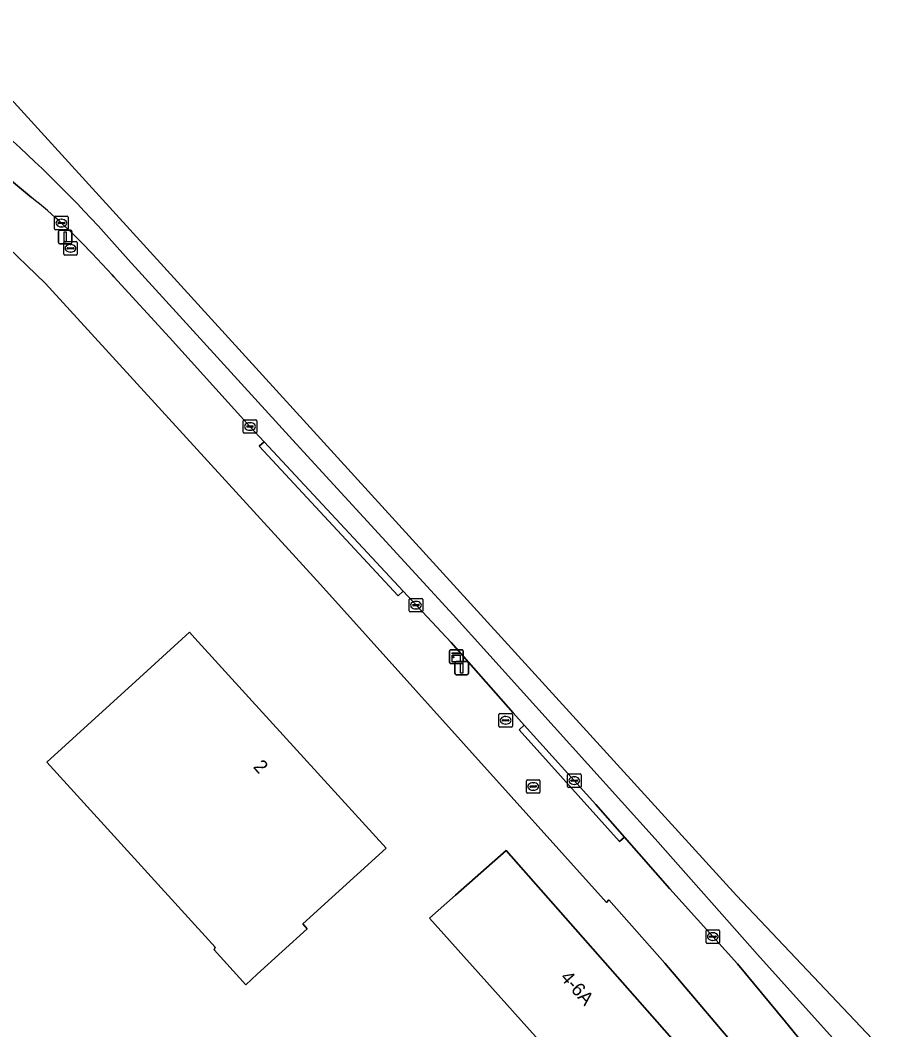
# Model space of a CAD drawing. Extents: x 161347 to 161881, y 382161 to 382804.
# Drawn here: x 161569.6 to 161633.8, y 382662 to 382736.8 of the extents above; entities that cross this region are included whole.
import ezdxf

# ---------------------------------------------------------------- set-up
doc = ezdxf.new("R2010")
doc.units = 0
for name, color, linetype in [('IMGEO_Brandkraan', 7, 'Continuous'), ('IMGEO_Erf', 7, 'Continuous'), ('IMGEO_Fietspad_gesloten', 7, 'Continuous'), ('IMGEO_Kast', 7, 'Continuous'), ('IMGEO_Kolk', 7, 'Continuous'), ('IMGEO_Lichtmast', 7, 'Continuous'), ('IMGEO_Pand', 7, 'Continuous'), ('IMGEO_Pand_nummerreeks', 7, 'Continuous'), ('IMGEO_Rijbaan_lokaal_gesloten', 7, 'Continuous'), ('IMGEO_Rioolput', 7, 'Continuous'), ('IMGEO_Voetpad_open', 7, 'Continuous')]:
    doc.layers.add(name, color=color, linetype=linetype)

msp = doc.modelspace()

# ---------------------------------------------------------------- linework, layer by layer
at = {"layer": 'IMGEO_Brandkraan'}
for p, q in [((161607.087, 382679.598), (161607.087, 382680.45)), ((161607.162, 382680.524), (161608.014, 382680.524)), ((161607.346, 382680.018), (161607.346, 382680.03)), ((161607.784, 382679.981), (161607.386, 382679.981)), ((161607.389, 382680.067), (161607.787, 382680.067)), ((161607.575, 382680.304), (161607.6, 382680.304)), ((161607.83, 382680.03), (161607.83, 382680.018)), ((161608.088, 382680.45), (161608.088, 382679.598)), ((161608.014, 382679.524), (161607.162, 382679.524)), ((161607.598, 382679.744), (161607.573, 382679.744))]:
    msp.add_line(p, q, dxfattribs=at)
for points in [[(161607.087, 382679.598), (161607.087, 382680.45)], [(161607.162, 382680.524), (161608.014, 382680.524)], [(161608.088, 382680.45), (161608.088, 382679.598)], [(161608.014, 382679.524), (161607.162, 382679.524)]]:
    msp.add_lwpolyline(points, dxfattribs=at)
for centre, radius, start, end in [((161607.164, 382680.448), 0.0765, 91.55205, 178.44795), ((161607.164, 382680.448), 0.0765, 91.55205, 178.44795), ((161607.386, 382680.027), 0.0403, 85.87752, 175.75265), ((161607.383, 382680.017), 0.0366, 178.93798, 274.71019), ((161607.787, 382680.024), 0.043, 264.86636, 352.45326), ((161607.791, 382680.029), 0.0386, 1.73085, 96.63898), ((161608.012, 382680.448), 0.0765, 1.55205, 88.44795), ((161608.012, 382680.448), 0.0765, 1.55205, 88.44795), ((161607.164, 382679.6), 0.0765, 181.55205, 268.44795), ((161607.164, 382679.6), 0.0765, 181.55205, 268.44795), ((161608.012, 382679.6), 0.0765, 271.55205, 358.44795), ((161608.012, 382679.6), 0.0765, 271.55205, 358.44795)]:
    msp.add_arc(centre, radius, start, end, dxfattribs=at)
for centre, major_axis, ratio, start_param, end_param in [((161607.574, 382680.024), (-0.387, 0.002), 0.722429, 4.712389, 7.853982), ((161607.599, 382680.024), (-0.39, 0.002), 0.717154, 1.570796, 4.712389)]:
    msp.add_ellipse(centre, major_axis=major_axis, ratio=ratio, start_param=start_param, end_param=end_param, dxfattribs=at)
at = {"layer": 'IMGEO_Erf'}
for points in [[(161591.856, 382694.988), (161571.485, 382717.274), (161568.031, 382720.568), (161555.239, 382731.179), (161554.063, 382732.154)], [(161628.148, 382654.156), (161617.321, 382666.942), (161613.19, 382671.62), (161613.021, 382671.42), (161591.856, 382694.988)]]:
    msp.add_lwpolyline(points, dxfattribs=at)
for points in [[(161571.579, 382681.821), (161578.45, 382688.079), (161582.146, 382691.445), (161582.55, 382691.001), (161586.536, 382686.624), (161596.704, 382675.461), (161590.534, 382669.841), (161590.862, 382669.482), (161587.166, 382666.115), (161586.317, 382665.342), (161583.975, 382667.913), (161584.045, 382668.134)], [(161613.901, 382654.655), (161599.917, 382670.282), (161601.837, 382671.975), (161605.587, 382675.281), (161621.16, 382657.617), (161617.611, 382654.487), (161621.256, 382649.017), (161611.371, 382642.428), (161608.598, 382646.589), (161606.558, 382649.651)]]:
    msp.add_lwpolyline(points, close=True, dxfattribs=at)
at = {"layer": 'IMGEO_Fietspad_gesloten'}
for points in [[(161566.876, 382729.794), (161565.588, 382730.912), (161565.541, 382730.953), (161563.827, 382729.146), (161570.459, 382723.644)], [(161706.007, 382577.787), (161673.989, 382613.712), (161653.899, 382634.564), (161636.579, 382653.807), (161636.242, 382654.182), (161624.391, 382667.348), (161616.607, 382676.142), (161601.665, 382692.722), (161589.767, 382705.692), (161577.619, 382719.049), (161575.378, 382721.548)], [(161574.947, 382719.489), (161576.417, 382717.907), (161576.552, 382717.761), (161580.679, 382713.283), (161586.624, 382706.683), (161587.674, 382705.553), (161597.956, 382694.49), (161601.503, 382690.673), (161606.094, 382685.466), (161606.913, 382684.561), (161612.225, 382678.689), (161614.343, 382676.276), (161617.707, 382672.442), (161622.699, 382666.884), (161626.262, 382662.585), (161628.402, 382659.955), (161631.077, 382656.546), (161631.214, 382656.385), (161631.541, 382655.956), (161631.782, 382655.692), (161639.863, 382646.847)]]:
    msp.add_lwpolyline(points, dxfattribs=at)
for centre, radius, start, end in [((161490.366, 382642.402), 116.151, 42.95321, 48.79823), ((161543.579, 382690.108), 42.979, 43.12627, 51.28657)]:
    msp.add_arc(centre, radius, start, end, dxfattribs=at)
at = {"layer": 'IMGEO_Kast'}
for p, q in [((161601.397, 382689.21), (161601.397, 382690.051)), ((161601.397, 382690.051), (161601.397, 382689.21)), ((161601.472, 382690.135), (161602.313, 382690.135)), ((161602.313, 382690.135), (161601.472, 382690.135)), ((161602.397, 382690.06), (161602.397, 382689.219)), ((161602.397, 382689.219), (161602.397, 382690.06)), ((161602.322, 382689.135), (161601.481, 382689.135)), ((161601.481, 382689.135), (161602.322, 382689.135))]:
    msp.add_line(p, q, dxfattribs=at)
for points in [[(161601.592, 382689.925), (161602.192, 382689.925), (161602.192, 382689.84), (161601.592, 382689.84), (161601.592, 382689.925)], [(161601.592, 382689.75), (161602.192, 382689.75), (161602.192, 382689.261), (161601.592, 382689.261), (161601.592, 382689.75)]]:
    msp.add_lwpolyline(points, dxfattribs=at)
msp.add_circle((161601.676, 382689.599), 0.0377, dxfattribs=at)
for centre, start, end in [((161601.475, 382690.057), 92.4484, 184.28452), ((161601.475, 382690.057), 92.4484, 184.28452), ((161602.319, 382690.057), 2.4484, 94.28452), ((161602.319, 382690.057), 2.4484, 94.28452), ((161601.475, 382689.213), 182.4484, 274.28452), ((161601.475, 382689.213), 182.4484, 274.28452), ((161602.319, 382689.213), 272.4484, 4.28452), ((161602.319, 382689.213), 272.4484, 4.28452)]:
    msp.add_arc(centre, 0.0779, start, end, dxfattribs=at)
at = {"layer": 'IMGEO_Kolk'}
for p, q in [((161572.167, 382721.321), (161572.167, 382722.173)), ((161572.242, 382722.247), (161573.094, 382722.247)), ((161572.426, 382721.741), (161572.426, 382721.753)), ((161572.864, 382721.704), (161572.466, 382721.704)), ((161572.469, 382721.79), (161572.867, 382721.79)), ((161572.655, 382722.027), (161572.68, 382722.027)), ((161572.91, 382721.753), (161572.91, 382721.741)), ((161573.168, 382722.173), (161573.168, 382721.321)), ((161573.094, 382721.247), (161572.242, 382721.247)), ((161572.678, 382721.467), (161572.653, 382721.467)), ((161586.126, 382706.256), (161586.126, 382707.108)), ((161586.201, 382707.182), (161587.053, 382707.182)), ((161586.428, 382706.725), (161586.826, 382706.725)), ((161586.614, 382706.962), (161586.639, 382706.962)), ((161587.127, 382707.108), (161587.127, 382706.256)), ((161587.053, 382706.182), (161586.201, 382706.182)), ((161586.385, 382706.676), (161586.385, 382706.688)), ((161586.823, 382706.639), (161586.425, 382706.639)), ((161586.637, 382706.402), (161586.612, 382706.402)), ((161586.869, 382706.688), (161586.869, 382706.676)), ((161598.406, 382693.021), (161598.406, 382693.873)), ((161598.481, 382693.947), (161599.333, 382693.947)), ((161598.665, 382693.441), (161598.665, 382693.453)), ((161599.103, 382693.404), (161598.705, 382693.404)), ((161598.708, 382693.49), (161599.106, 382693.49)), ((161598.894, 382693.727), (161598.919, 382693.727)), ((161599.149, 382693.453), (161599.149, 382693.441)), ((161599.407, 382693.873), (161599.407, 382693.021)), ((161599.333, 382692.947), (161598.481, 382692.947)), ((161598.917, 382693.167), (161598.892, 382693.167)), ((161610.124, 382680.03), (161610.124, 382680.882)), ((161610.199, 382680.956), (161611.051, 382680.956)), ((161610.612, 382680.736), (161610.637, 382680.736)), ((161611.125, 382680.882), (161611.125, 382680.03)), ((161611.051, 382679.956), (161610.199, 382679.956)), ((161610.383, 382680.45), (161610.383, 382680.462)), ((161610.821, 382680.413), (161610.423, 382680.413)), ((161610.426, 382680.499), (161610.824, 382680.499)), ((161610.635, 382680.176), (161610.61, 382680.176)), ((161610.867, 382680.462), (161610.867, 382680.45)), ((161620.382, 382668.478), (161620.382, 382669.33)), ((161620.457, 382669.404), (161621.309, 382669.404)), ((161621.383, 382669.33), (161621.383, 382668.478)), ((161620.641, 382668.898), (161620.641, 382668.91)), ((161621.079, 382668.861), (161620.681, 382668.861)), ((161620.684, 382668.947), (161621.082, 382668.947)), ((161620.893, 382668.624), (161620.868, 382668.624)), ((161620.87, 382669.184), (161620.895, 382669.184)), ((161621.125, 382668.91), (161621.125, 382668.898)), ((161621.309, 382668.404), (161620.457, 382668.404))]:
    msp.add_line(p, q, dxfattribs=at)
for points in [[(161572.167, 382721.321), (161572.167, 382722.173)], [(161572.242, 382722.247), (161573.094, 382722.247)], [(161573.168, 382722.173), (161573.168, 382721.321)], [(161573.094, 382721.247), (161572.242, 382721.247)], [(161586.126, 382706.256), (161586.126, 382707.108)], [(161586.201, 382707.182), (161587.053, 382707.182)], [(161587.127, 382707.108), (161587.127, 382706.256)], [(161587.053, 382706.182), (161586.201, 382706.182)], [(161598.406, 382693.021), (161598.406, 382693.873)], [(161598.481, 382693.947), (161599.333, 382693.947)], [(161599.407, 382693.873), (161599.407, 382693.021)], [(161599.333, 382692.947), (161598.481, 382692.947)], [(161610.124, 382680.03), (161610.124, 382680.882)], [(161610.199, 382680.956), (161611.051, 382680.956)], [(161611.125, 382680.882), (161611.125, 382680.03)], [(161611.051, 382679.956), (161610.199, 382679.956)], [(161620.382, 382668.478), (161620.382, 382669.33)], [(161620.457, 382669.404), (161621.309, 382669.404)], [(161621.383, 382669.33), (161621.383, 382668.478)], [(161621.309, 382668.404), (161620.457, 382668.404)]]:
    msp.add_lwpolyline(points, dxfattribs=at)
for centre, radius, start, end in [((161572.244, 382722.171), 0.0765, 91.55205, 178.44795), ((161572.244, 382722.171), 0.0765, 91.55205, 178.44795), ((161572.466, 382721.75), 0.0403, 85.87752, 175.75265), ((161572.463, 382721.74), 0.0366, 178.93798, 274.71019), ((161572.867, 382721.747), 0.043, 264.86636, 352.45326), ((161572.871, 382721.752), 0.0386, 1.73085, 96.63898), ((161573.092, 382722.171), 0.0765, 1.55205, 88.44795), ((161573.092, 382722.171), 0.0765, 1.55205, 88.44795), ((161572.244, 382721.323), 0.0765, 181.55205, 268.44795), ((161572.244, 382721.323), 0.0765, 181.55205, 268.44795), ((161573.092, 382721.323), 0.0765, 271.55205, 358.44795), ((161573.092, 382721.323), 0.0765, 271.55205, 358.44795), ((161586.203, 382707.106), 0.0765, 91.55205, 178.44795), ((161586.203, 382707.106), 0.0765, 91.55205, 178.44795), ((161586.425, 382706.685), 0.0403, 85.87752, 175.75265), ((161586.83, 382706.687), 0.0386, 1.73085, 96.63898), ((161587.051, 382707.106), 0.0765, 1.55205, 88.44795), ((161587.051, 382707.106), 0.0765, 1.55205, 88.44795), ((161586.203, 382706.258), 0.0765, 181.55205, 268.44795), ((161586.203, 382706.258), 0.0765, 181.55205, 268.44795), ((161586.422, 382706.675), 0.0366, 178.93798, 274.71019), ((161586.826, 382706.682), 0.043, 264.86636, 352.45326), ((161587.051, 382706.258), 0.0765, 271.55205, 358.44795), ((161587.051, 382706.258), 0.0765, 271.55205, 358.44795), ((161598.483, 382693.871), 0.0765, 91.55205, 178.44795), ((161598.483, 382693.871), 0.0765, 91.55205, 178.44795), ((161598.705, 382693.45), 0.0403, 85.87752, 175.75265), ((161598.702, 382693.44), 0.0366, 178.93798, 274.71019), ((161599.106, 382693.447), 0.043, 264.86636, 352.45326), ((161599.11, 382693.452), 0.0386, 1.73085, 96.63898), ((161599.331, 382693.871), 0.0765, 1.55205, 88.44795), ((161599.331, 382693.871), 0.0765, 1.55205, 88.44795), ((161598.483, 382693.023), 0.0765, 181.55205, 268.44795), ((161598.483, 382693.023), 0.0765, 181.55205, 268.44795), ((161599.331, 382693.023), 0.0765, 271.55205, 358.44795), ((161599.331, 382693.023), 0.0765, 271.55205, 358.44795), ((161610.201, 382680.88), 0.0765, 91.55205, 178.44795), ((161610.201, 382680.88), 0.0765, 91.55205, 178.44795), ((161611.049, 382680.88), 0.0765, 1.55205, 88.44795), ((161611.049, 382680.88), 0.0765, 1.55205, 88.44795), ((161610.201, 382680.032), 0.0765, 181.55205, 268.44795), ((161610.201, 382680.032), 0.0765, 181.55205, 268.44795), ((161610.423, 382680.459), 0.0403, 85.87752, 175.75265), ((161610.42, 382680.449), 0.0366, 178.93798, 274.71019), ((161610.824, 382680.456), 0.043, 264.86636, 352.45326), ((161610.828, 382680.461), 0.0386, 1.73085, 96.63898), ((161611.049, 382680.032), 0.0765, 271.55205, 358.44795), ((161611.049, 382680.032), 0.0765, 271.55205, 358.44795), ((161620.459, 382669.328), 0.0765, 91.55205, 178.44795), ((161620.459, 382669.328), 0.0765, 91.55205, 178.44795), ((161621.307, 382669.328), 0.0765, 1.55205, 88.44795), ((161621.307, 382669.328), 0.0765, 1.55205, 88.44795), ((161620.681, 382668.907), 0.0403, 85.87752, 175.75265), ((161620.678, 382668.897), 0.0366, 178.93798, 274.71019), ((161621.082, 382668.904), 0.043, 264.86636, 352.45326), ((161621.086, 382668.909), 0.0386, 1.73085, 96.63898), ((161620.459, 382668.48), 0.0765, 181.55205, 268.44795), ((161620.459, 382668.48), 0.0765, 181.55205, 268.44795), ((161621.307, 382668.48), 0.0765, 271.55205, 358.44795), ((161621.307, 382668.48), 0.0765, 271.55205, 358.44795)]:
    msp.add_arc(centre, radius, start, end, dxfattribs=at)
for centre, major_axis, ratio, start_param, end_param in [((161572.654, 382721.747), (-0.387, 0.002), 0.722429, 4.712389, 7.853982), ((161572.679, 382721.747), (-0.39, 0.002), 0.717154, 1.570796, 4.712389), ((161586.613, 382706.682), (-0.387, 0.002), 0.722429, 4.712389, 7.853982), ((161586.638, 382706.682), (-0.39, 0.002), 0.717154, 1.570796, 4.712389), ((161598.893, 382693.447), (-0.387, 0.002), 0.722429, 4.712389, 7.853982), ((161598.918, 382693.447), (-0.39, 0.002), 0.717154, 1.570796, 4.712389), ((161610.611, 382680.456), (-0.387, 0.002), 0.722429, 4.712389, 7.853982), ((161610.636, 382680.456), (-0.39, 0.002), 0.717154, 1.570796, 4.712389), ((161620.869, 382668.904), (-0.387, 0.002), 0.722429, 4.712389, 7.853982), ((161620.894, 382668.904), (-0.39, 0.002), 0.717154, 1.570796, 4.712389)]:
    msp.add_ellipse(centre, major_axis=major_axis, ratio=ratio, start_param=start_param, end_param=end_param, dxfattribs=at)
at = {"layer": 'IMGEO_Lichtmast'}
for p, q in [((161572.443, 382720.315), (161572.443, 382721.115)), ((161572.443, 382721.115), (161572.443, 382720.315)), ((161572.543, 382721.215), (161573.333, 382721.215)), ((161573.333, 382721.215), (161572.543, 382721.215)), ((161573.433, 382721.115), (161573.433, 382720.315)), ((161573.433, 382720.315), (161573.433, 382721.115)), ((161573.333, 382720.215), (161572.543, 382720.215)), ((161572.543, 382720.215), (161573.333, 382720.215)), ((161601.796, 382688.388), (161601.796, 382689.188)), ((161601.796, 382689.188), (161601.796, 382688.388)), ((161601.896, 382689.288), (161602.686, 382689.288)), ((161602.686, 382689.288), (161601.896, 382689.288)), ((161602.786, 382689.188), (161602.786, 382688.388)), ((161602.786, 382688.388), (161602.786, 382689.188)), ((161602.686, 382688.288), (161601.896, 382688.288)), ((161601.896, 382688.288), (161602.686, 382688.288))]:
    msp.add_line(p, q, dxfattribs=at)
for points in [[(161572.863, 382721.09), (161573.013, 382721.09), (161573.013, 382720.34), (161572.863, 382720.34), (161572.863, 382721.09)], [(161602.216, 382689.163), (161602.366, 382689.163), (161602.366, 382688.413), (161602.216, 382688.413), (161602.216, 382689.163)]]:
    msp.add_lwpolyline(points, dxfattribs=at)
for centre, start, end in [((161572.543, 382721.115), 90, 180), ((161572.543, 382721.115), 90, 180), ((161573.333, 382721.115), 0, 90), ((161573.333, 382721.115), 360, 90), ((161572.543, 382720.315), 180, 270), ((161572.543, 382720.315), 180, 270), ((161573.333, 382720.315), 270, 0), ((161573.333, 382720.315), 270, 0), ((161601.896, 382689.188), 90, 180), ((161601.896, 382689.188), 90, 180), ((161602.686, 382689.188), 0, 90), ((161602.686, 382689.188), 360, 90), ((161601.896, 382688.388), 180, 270), ((161601.896, 382688.388), 180, 270), ((161602.686, 382688.388), 270, 0), ((161602.686, 382688.388), 270, 0)]:
    msp.add_arc(centre, 0.1, start, end, dxfattribs=at)
at = {"layer": 'IMGEO_Pand'}
for points in [[(161587.166, 382666.115), (161590.862, 382669.482), (161590.534, 382669.841), (161596.704, 382675.461), (161586.536, 382686.624), (161582.55, 382691.001), (161582.146, 382691.445), (161578.45, 382688.079), (161571.579, 382681.821), (161584.045, 382668.134), (161583.975, 382667.913), (161586.317, 382665.342)], [(161608.598, 382646.589), (161611.371, 382642.428), (161621.256, 382649.017), (161617.611, 382654.487), (161621.16, 382657.617), (161605.587, 382675.281), (161601.837, 382671.975), (161599.917, 382670.282), (161613.901, 382654.655), (161606.558, 382649.651)]]:
    msp.add_lwpolyline(points, close=True, dxfattribs=at)
at = {"layer": 'IMGEO_Rijbaan_lokaal_gesloten'}
for points in [[(161780.196, 382571.153), (161779.525, 382578.285), (161728.827, 382571.874), (161701.238, 382588.176), (161661.586, 382630.771), (161622.627, 382671.947), (161592.087, 382705.487), (161563.602, 382736.77)], [(161575.378, 382721.548), (161577.619, 382719.049), (161589.767, 382705.692), (161601.665, 382692.722), (161616.607, 382676.142), (161624.391, 382667.348), (161636.242, 382654.182), (161636.579, 382653.807), (161653.899, 382634.564), (161673.989, 382613.712), (161706.007, 382577.787), (161705.643, 382575.646), (161721.925, 382567.837)]]:
    msp.add_lwpolyline(points, dxfattribs=at)
msp.add_arc((161490.366, 382642.402), 116.151, 42.95321, 48.79823, dxfattribs=at)
at = {"layer": 'IMGEO_Rioolput'}
for p, q in [((161572.84, 382719.451), (161572.84, 382720.303)), ((161572.915, 382720.377), (161573.767, 382720.377)), ((161573.328, 382720.157), (161573.353, 382720.157)), ((161573.841, 382720.303), (161573.841, 382719.451)), ((161573.099, 382719.871), (161573.099, 382719.883)), ((161573.537, 382719.834), (161573.139, 382719.834)), ((161573.142, 382719.92), (161573.54, 382719.92)), ((161573.351, 382719.597), (161573.326, 382719.597)), ((161573.583, 382719.883), (161573.583, 382719.871)), ((161573.767, 382719.377), (161572.915, 382719.377)), ((161605.051, 382684.497), (161605.051, 382685.349)), ((161605.126, 382685.423), (161605.978, 382685.423)), ((161605.539, 382685.203), (161605.564, 382685.203)), ((161606.052, 382685.349), (161606.052, 382684.497)), ((161605.978, 382684.423), (161605.126, 382684.423)), ((161605.31, 382684.917), (161605.31, 382684.929)), ((161605.748, 382684.88), (161605.35, 382684.88)), ((161605.353, 382684.966), (161605.751, 382684.966)), ((161605.562, 382684.643), (161605.537, 382684.643)), ((161605.794, 382684.929), (161605.794, 382684.917))]:
    msp.add_line(p, q, dxfattribs=at)
for points in [[(161572.84, 382719.451), (161572.84, 382720.303)], [(161572.915, 382720.377), (161573.767, 382720.377)], [(161573.841, 382720.303), (161573.841, 382719.451)], [(161573.767, 382719.377), (161572.915, 382719.377)], [(161605.051, 382684.497), (161605.051, 382685.349)], [(161605.126, 382685.423), (161605.978, 382685.423)], [(161606.052, 382685.349), (161606.052, 382684.497)], [(161605.978, 382684.423), (161605.126, 382684.423)]]:
    msp.add_lwpolyline(points, dxfattribs=at)
for centre, radius, start, end in [((161572.917, 382720.301), 0.0765, 91.55205, 178.44795), ((161572.917, 382720.301), 0.0765, 91.55205, 178.44795), ((161573.765, 382720.301), 0.0765, 1.55205, 88.44795), ((161573.765, 382720.301), 0.0765, 1.55205, 88.44795), ((161572.917, 382719.453), 0.0765, 181.55205, 268.44795), ((161572.917, 382719.453), 0.0765, 181.55205, 268.44795), ((161573.139, 382719.88), 0.0403, 85.87752, 175.75265), ((161573.136, 382719.87), 0.0366, 178.93798, 274.71019), ((161573.54, 382719.877), 0.043, 264.86636, 352.45326), ((161573.544, 382719.882), 0.0386, 1.73085, 96.63898), ((161573.765, 382719.453), 0.0765, 271.55205, 358.44795), ((161573.765, 382719.453), 0.0765, 271.55205, 358.44795), ((161605.128, 382685.347), 0.0765, 91.55205, 178.44795), ((161605.128, 382685.347), 0.0765, 91.55205, 178.44795), ((161605.976, 382685.347), 0.0765, 1.55205, 88.44795), ((161605.976, 382685.347), 0.0765, 1.55205, 88.44795), ((161605.128, 382684.499), 0.0765, 181.55205, 268.44795), ((161605.128, 382684.499), 0.0765, 181.55205, 268.44795), ((161605.35, 382684.926), 0.0403, 85.87752, 175.75265), ((161605.347, 382684.916), 0.0366, 178.93798, 274.71019), ((161605.751, 382684.923), 0.043, 264.86636, 352.45326), ((161605.755, 382684.928), 0.0386, 1.73085, 96.63898), ((161605.976, 382684.499), 0.0765, 271.55205, 358.44795), ((161605.976, 382684.499), 0.0765, 271.55205, 358.44795)]:
    msp.add_arc(centre, radius, start, end, dxfattribs=at)
for centre, major_axis, ratio, start_param, end_param in [((161573.327, 382719.877), (-0.387, 0.002), 0.722429, 4.712389, 7.853982), ((161573.352, 382719.877), (-0.39, 0.002), 0.717154, 1.570796, 4.712389), ((161605.538, 382684.923), (-0.387, 0.002), 0.722429, 4.712389, 7.853982), ((161605.563, 382684.923), (-0.39, 0.002), 0.717154, 1.570796, 4.712389)]:
    msp.add_ellipse(centre, major_axis=major_axis, ratio=ratio, start_param=start_param, end_param=end_param, dxfattribs=at)
at = {"layer": 'IMGEO_Voetpad_open'}
for points in [[(161570.459, 382723.644), (161563.827, 382729.146), (161562.685, 382730.093), (161559.548, 382732.78), (161558.194, 382734.023), (161555.239, 382731.179), (161568.031, 382720.568), (161571.485, 382717.274), (161591.856, 382694.988), (161613.021, 382671.42), (161613.19, 382671.62), (161617.321, 382666.942), (161628.148, 382654.156)], [(161622.699, 382666.884), (161617.707, 382672.442), (161614.343, 382676.276), (161613.971, 382675.943), (161606.541, 382684.228), (161606.913, 382684.561), (161606.094, 382685.466), (161601.503, 382690.673), (161597.956, 382694.49), (161597.59, 382694.15), (161587.308, 382705.213), (161587.674, 382705.553), (161586.624, 382706.683), (161580.679, 382713.283), (161576.552, 382717.761), (161576.417, 382717.907), (161574.947, 382719.489)], [(161630.957, 382655.494), (161630.647, 382655.913), (161631.214, 382656.385), (161631.077, 382656.546), (161628.402, 382659.955), (161626.262, 382662.585), (161622.699, 382666.884)]]:
    msp.add_lwpolyline(points, dxfattribs=at)
for points in [[(161587.674, 382705.553), (161587.308, 382705.213), (161597.59, 382694.15), (161597.956, 382694.49)], [(161614.343, 382676.276), (161612.225, 382678.689), (161606.913, 382684.561), (161606.541, 382684.228), (161613.971, 382675.943)]]:
    msp.add_lwpolyline(points, close=True, dxfattribs=at)
msp.add_arc((161543.579, 382690.108), 42.979, 43.12627, 51.28657, dxfattribs=at)

# ---------------------------------------------------------------- texts
at = {"layer": 'IMGEO_Pand_nummerreeks'}
for s, rotation, p in [('2', 312.32681, (161586.813, 382681.449)), ('4-6A', 311.40016, (161609.537, 382665.84))]:
    msp.add_text(s, height=1, rotation=rotation, dxfattribs=at).set_placement(p)

doc.saveas('drawing.dxf')
